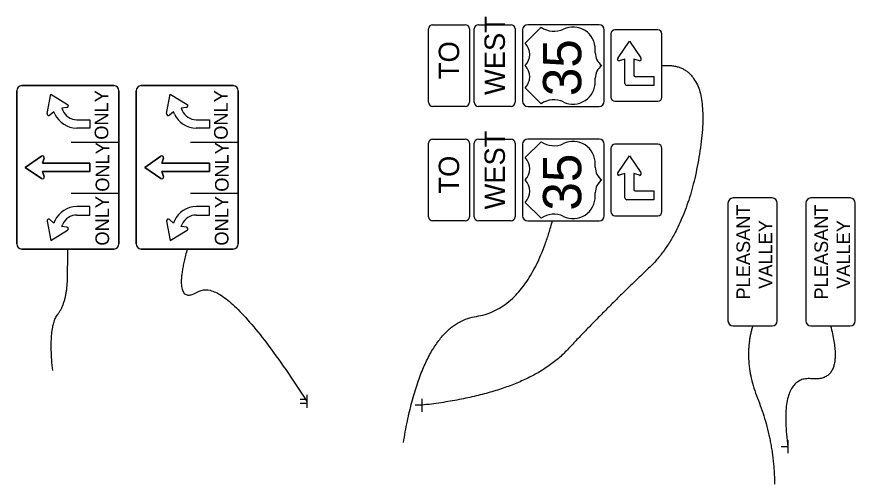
# Model space of a CAD drawing. Extents: x 1817563 to 1822411, y 498049 to 499279.
# Drawn here: x 1817747.4 to 1817952.7, y 499164.3 to 499278.8 of the extents above; entities that cross this region are included whole.
import ezdxf

# ---------------------------------------------------------------- set-up
doc = ezdxf.new("R2010")
doc.units = 0
doc.layers.add('PM_X_Stop_Line', color=7, linetype='Continuous')
doc.layers.add('SC_Scratch2', color=7, linetype='Continuous')

msp = doc.modelspace()

# ---------------------------------------------------------------- linework, layer by layer
at = {"layer": 'PM_X_Stop_Line'}
for p, q in [((1817848.25, 499257.84), (1817848.25, 499275.84)), ((1817849.25, 499276.84), (1817857.25, 499276.84)), ((1817858.25, 499275.84), (1817858.25, 499257.84)), ((1817859.46, 499257.84), (1817859.46, 499275.84)), ((1817860.46, 499276.84), (1817868.46, 499276.84)), ((1817869.46, 499275.84), (1817869.46, 499257.84)), ((1817875.81, 499276.22), (1817871.9, 499272.31)), ((1817904.41, 499275.59), (1817893.91, 499275.59)), ((1817892.91, 499274.59), (1817892.91, 499259.09)), ((1817905.41, 499259.09), (1817905.41, 499274.59)), ((1817894.65, 499268.7), (1817897.44, 499272.78)), ((1817897.44, 499272.78), (1817900.24, 499268.7)), ((1817889.09, 499269.97), (1817889.09, 499270.75)), ((1817896.35, 499268.4), (1817894.94, 499267.99)), ((1817896.35, 499262.47), (1817896.35, 499268.4)), ((1817899.94, 499267.99), (1817898.54, 499268.4)), ((1817898.54, 499268.4), (1817898.54, 499264.5)), ((1817889.09, 499262.94), (1817889.09, 499263.72)), ((1817898.85, 499264.19), (1817903.38, 499264.19)), ((1817903.38, 499264.19), (1817903.38, 499262)), ((1817871.9, 499261.37), (1817875.81, 499257.47)), ((1817896.35, 499262.47), (1817896.35, 499262.47)), ((1817903.38, 499262), (1817896.82, 499262)), ((1817784.13, 499255.08), (1817785.01, 499259.84)), ((1817785.01, 499259.84), (1817789.14, 499257.31)), ((1817857.25, 499256.84), (1817849.25, 499256.84)), ((1817868.46, 499256.84), (1817860.46, 499256.84)), ((1817893.91, 499258.09), (1817904.41, 499258.09)), ((1817785.78, 499255.54), (1817784.81, 499254.69)), ((1817786.04, 499254.96), (1817785.78, 499255.54)), ((1817788.97, 499256.54), (1817787.69, 499256.39)), ((1817787.69, 499256.39), (1817787.94, 499255.81)), ((1817791.37, 499253.59), (1817794.6, 499253.59)), ((1817794.6, 499253.59), (1817794.6, 499251.5)), ((1817794.6, 499251.5), (1817791.37, 499251.5)), ((1817790.01, 499248.06), (1817801.68, 499248.06)), ((1817778.76, 499241.92), (1817782.75, 499244.66)), ((1817782.75, 499244.66), (1817778.76, 499241.92)), ((1817783.38, 499244.19), (1817783, 499242.96)), ((1817783, 499242.96), (1817783.38, 499244.19)), ((1817783, 499242.96), (1817794.6, 499242.96)), ((1817794.6, 499242.96), (1817783, 499242.96)), ((1817794.6, 499242.96), (1817794.6, 499240.88)), ((1817794.6, 499240.88), (1817794.6, 499242.96)), ((1817782.75, 499239.18), (1817778.76, 499241.92)), ((1817778.76, 499241.92), (1817782.75, 499239.18)), ((1817794.6, 499240.88), (1817783, 499240.88)), ((1817783, 499240.88), (1817783.38, 499239.65)), ((1817783.38, 499239.65), (1817783, 499240.88)), ((1817783, 499240.88), (1817794.6, 499240.88)), ((1817790.01, 499235.56), (1817801.68, 499235.56)), ((1817794.6, 499232.34), (1817791.37, 499232.34)), ((1817794.6, 499230.25), (1817794.6, 499232.34)), ((1817791.37, 499230.25), (1817794.6, 499230.25)), ((1817784.13, 499228.75), (1817785.01, 499224)), ((1817785.78, 499228.29), (1817784.81, 499229.14)), ((1817786.04, 499228.88), (1817785.78, 499228.29)), ((1817785.01, 499224), (1817789.14, 499226.53)), ((1817787.69, 499227.45), (1817787.94, 499228.03)), ((1817788.97, 499227.3), (1817787.69, 499227.45)), ((1817818.46, 499185.09), (1817816.86, 499185.09)), ((1817818.46, 499186.21), (1817818.46, 499183.01)), ((1817846.6, 499185.27), (1817846.6, 499182.07)), ((1817818.46, 499184.13), (1817816.86, 499184.13)), ((1817818.46, 499184.61), (1817818.46, 499184.61)), ((1817818.46, 499184.61), (1817818.46, 499184.61)), ((1817846.6, 499183.67), (1817845, 499183.67)), ((1817936.23, 499175.13), (1817936.23, 499171.93)), ((1817936.23, 499173.53), (1817934.63, 499173.53))]:
    msp.add_line(p, q, dxfattribs=at)
for points in [[(1817871.28, 499275.59), (1817871.28, 499258.09)], [(1817890.03, 499276.84), (1817872.53, 499276.84)], [(1817891.28, 499258.09), (1817891.28, 499275.59)], [(1817777.93, 499261.92), (1817800.43, 499261.92)], [(1817800.43, 499261.92), (1817777.93, 499261.92)], [(1817776.68, 499223.17), (1817776.68, 499260.67)], [(1817776.68, 499260.67), (1817776.68, 499223.17)], [(1817801.68, 499260.67), (1817801.68, 499223.17)], [(1817801.68, 499223.17), (1817801.68, 499260.67)], [(1817872.53, 499256.84), (1817890.03, 499256.84)], [(1817951.48, 499234.42), (1817941.89, 499234.42)], [(1817940.64, 499233.17), (1817940.64, 499204.34)], [(1817952.73, 499204.34), (1817952.73, 499233.17)], [(1817800.43, 499221.92), (1817777.93, 499221.92)], [(1817777.93, 499221.92), (1817800.43, 499221.92)], [(1817941.89, 499203.09), (1817951.48, 499203.09)]]:
    msp.add_lwpolyline(points, dxfattribs=at)
for centre, radius, start, end in [((1817849.25, 499275.84), 1, 90, 180), ((1817857.25, 499275.84), 1, 0, 90), ((1817860.46, 499275.84), 1, 90, 180), ((1817868.46, 499275.84), 1, 0, 90), ((1817872.53, 499275.59), 1.25, 90, 180), ((1817878.95, 499280.7), 5.47, 234.9991, 295.4529), ((1817883.62, 499270.81), 5.47, 359.3617, 115.1681), ((1817890.03, 499275.59), 1.25, 0, 90), ((1817893.91, 499274.59), 1, 90, 180), ((1817904.41, 499274.59), 1, 0, 90), ((1817869.11, 499269.58), 3.91, 315.573, 44.427), ((1817893, 499269.97), 3.91, 180, 233.1301), ((1817894.94, 499268.4), 0.417, 135.0001, 269.9983), ((1817899.94, 499268.4), 0.417, 269.9983, 44.9999), ((1817869.11, 499264.11), 3.91, 315.573, 44.427), ((1817893, 499263.72), 3.91, 126.8699, 180), ((1817898.85, 499264.5), 0.312, 180, 270), ((1817777.93, 499260.67), 1.25, 90, 180), ((1817777.93, 499260.67), 1.25, 90, 180), ((1817800.43, 499260.67), 1.25, 360, 90), ((1817800.43, 499260.67), 1.25, 0, 90), ((1817883.62, 499262.87), 5.47, 244.8319, 0.6383), ((1817896.82, 499262.47), 0.469, 180, 270), ((1817893.91, 499259.09), 1, 180, 270), ((1817904.41, 499259.09), 1, 270, 0), ((1817788.92, 499256.95), 0.417, 276.5948, 58.4729), ((1817849.25, 499257.84), 1, 180, 270), ((1817857.25, 499257.84), 1, 270, 360), ((1817860.46, 499257.84), 1, 180, 270), ((1817868.46, 499257.84), 1, 270, 360), ((1817872.53, 499258.09), 1.25, 180, 270), ((1817878.95, 499252.99), 5.47, 64.5471, 125.0009), ((1817890.03, 499258.09), 1.25, 270, 360), ((1817784.54, 499255.01), 0.417, 169.4403, 311.3184), ((1817791.37, 499257.34), 5.83, 203.9101, 270), ((1817791.37, 499257.34), 3.75, 203.8986, 270), ((1817782.98, 499244.31), 0.417, 342.6382, 124.5163), ((1817782.98, 499244.31), 0.417, 342.6382, 124.5163), ((1817782.98, 499239.52), 0.417, 235.4837, 17.3618), ((1817782.98, 499239.52), 0.417, 235.4837, 17.3618), ((1817941.89, 499233.17), 1.25, 90, 180), ((1817951.48, 499233.17), 1.25, 360, 90), ((1817791.37, 499226.5), 5.83, 90, 156.0899), ((1817791.37, 499226.5), 3.75, 90, 156.1014), ((1817784.54, 499228.83), 0.417, 48.6816, 190.5597), ((1817788.92, 499226.89), 0.417, 301.5271, 83.4052), ((1817777.93, 499223.17), 1.25, 180, 270), ((1817777.93, 499223.17), 1.25, 180, 270), ((1817800.43, 499223.17), 1.25, 270, 360), ((1817800.43, 499223.17), 1.25, 270, 0), ((1817941.89, 499204.34), 1.25, 180, 270), ((1817951.48, 499204.34), 1.25, 270, 360)]:
    msp.add_arc(centre, radius, start, end, dxfattribs=at)
for points in [[(1817905.41, 499266.84), (1817917.72, 499267.86), (1817912.05, 499226.55), (1817891.94, 499207.57), (1817872.26, 499186.6), (1817846.6, 499183.67)], [(1817789.18, 499221.92), (1817785.22, 499207.53), (1817798.68, 499215.5), (1817818.46, 499184.61)], [(1817946.69, 499203.09), (1817950.33, 499189.3), (1817933.88, 499191.01), (1817936.23, 499173.53)]]:
    msp.add_open_spline(points, degree=2, dxfattribs=at)
at = {"layer": 'SC_Scratch2'}
for p, q in [((1817754.89, 499255.08), (1817755.78, 499259.84)), ((1817755.78, 499259.84), (1817759.9, 499257.31)), ((1817756.54, 499255.54), (1817755.57, 499254.69)), ((1817756.8, 499254.96), (1817756.54, 499255.54)), ((1817759.73, 499256.54), (1817758.45, 499256.39)), ((1817758.45, 499256.39), (1817758.7, 499255.81)), ((1817762.13, 499253.59), (1817765.36, 499253.59)), ((1817765.36, 499253.59), (1817765.36, 499251.5)), ((1817765.36, 499251.5), (1817762.13, 499251.5)), ((1817849.25, 499248.82), (1817857.25, 499248.82)), ((1817860.46, 499248.82), (1817868.46, 499248.82)), ((1817760.78, 499248.06), (1817772.44, 499248.06)), ((1817848.25, 499229.82), (1817848.25, 499247.82)), ((1817858.25, 499247.82), (1817858.25, 499229.82)), ((1817859.46, 499229.82), (1817859.46, 499247.82)), ((1817869.46, 499247.82), (1817869.46, 499229.82)), ((1817875.81, 499248.2), (1817871.9, 499244.29)), ((1817904.41, 499247.57), (1817893.91, 499247.57)), ((1817749.53, 499241.92), (1817753.51, 499244.66)), ((1817753.51, 499244.66), (1817749.53, 499241.92)), ((1817892.91, 499246.57), (1817892.91, 499231.07)), ((1817894.65, 499240.68), (1817897.44, 499244.76)), ((1817897.44, 499244.76), (1817900.24, 499240.68)), ((1817905.41, 499231.07), (1817905.41, 499246.57)), ((1817754.14, 499244.19), (1817753.76, 499242.96)), ((1817753.76, 499242.96), (1817754.14, 499244.19)), ((1817753.76, 499242.96), (1817765.36, 499242.96)), ((1817765.36, 499242.96), (1817753.76, 499242.96)), ((1817765.36, 499242.96), (1817765.36, 499240.88)), ((1817765.36, 499240.88), (1817765.36, 499242.96)), ((1817889.09, 499241.95), (1817889.09, 499242.73)), ((1817753.51, 499239.18), (1817749.53, 499241.92)), ((1817749.53, 499241.92), (1817753.51, 499239.18)), ((1817765.36, 499240.88), (1817753.76, 499240.88)), ((1817753.76, 499240.88), (1817754.14, 499239.65)), ((1817754.14, 499239.65), (1817753.76, 499240.88)), ((1817753.76, 499240.88), (1817765.36, 499240.88)), ((1817896.35, 499240.38), (1817894.94, 499239.97)), ((1817896.35, 499234.45), (1817896.35, 499240.38)), ((1817899.94, 499239.97), (1817898.54, 499240.38)), ((1817898.54, 499240.38), (1817898.54, 499236.48)), ((1817760.78, 499235.56), (1817772.44, 499235.56)), ((1817889.09, 499234.92), (1817889.09, 499235.7)), ((1817896.35, 499234.45), (1817896.35, 499234.45)), ((1817898.85, 499236.17), (1817903.38, 499236.17)), ((1817903.38, 499236.17), (1817903.38, 499233.98)), ((1817765.36, 499232.34), (1817762.13, 499232.34)), ((1817765.36, 499230.25), (1817765.36, 499232.34)), ((1817871.9, 499233.35), (1817875.81, 499229.45)), ((1817903.38, 499233.98), (1817896.82, 499233.98)), ((1817762.13, 499230.25), (1817765.36, 499230.25)), ((1817754.89, 499228.75), (1817755.78, 499224)), ((1817756.54, 499228.29), (1817755.57, 499229.14)), ((1817756.8, 499228.88), (1817756.54, 499228.29)), ((1817857.25, 499228.82), (1817849.25, 499228.82)), ((1817868.46, 499228.82), (1817860.46, 499228.82)), ((1817893.91, 499230.07), (1817904.41, 499230.07)), ((1817755.78, 499224), (1817759.9, 499226.53)), ((1817758.45, 499227.45), (1817758.7, 499228.03)), ((1817759.73, 499227.3), (1817758.45, 499227.45))]:
    msp.add_line(p, q, dxfattribs=at)
for points in [[(1817748.69, 499261.92), (1817771.19, 499261.92)], [(1817771.19, 499261.92), (1817748.69, 499261.92)], [(1817747.44, 499223.17), (1817747.44, 499260.67)], [(1817747.44, 499260.67), (1817747.44, 499223.17)], [(1817772.44, 499260.67), (1817772.44, 499223.17)], [(1817772.44, 499223.17), (1817772.44, 499260.67)], [(1817890.03, 499248.82), (1817872.53, 499248.82)], [(1817871.28, 499247.57), (1817871.28, 499230.07)], [(1817891.28, 499230.07), (1817891.28, 499247.57)], [(1817932.4, 499234.42), (1817922.81, 499234.42)], [(1817921.56, 499233.17), (1817921.56, 499204.34)], [(1817933.65, 499204.34), (1817933.65, 499233.17)], [(1817872.53, 499228.82), (1817890.03, 499228.82)], [(1817771.19, 499221.92), (1817748.69, 499221.92)], [(1817748.69, 499221.92), (1817771.19, 499221.92)], [(1817922.81, 499203.09), (1817932.4, 499203.09)]]:
    msp.add_lwpolyline(points, dxfattribs=at)
for centre, radius, start, end in [((1817748.69, 499260.67), 1.25, 90, 180), ((1817748.69, 499260.67), 1.25, 90, 180), ((1817771.19, 499260.67), 1.25, 360, 90), ((1817771.19, 499260.67), 1.25, 0, 90), ((1817759.68, 499256.95), 0.417, 276.5948, 58.4729), ((1817755.3, 499255.01), 0.417, 169.4403, 311.3184), ((1817762.13, 499257.34), 5.83, 203.9101, 270), ((1817762.13, 499257.34), 3.75, 203.8986, 270), ((1817849.25, 499247.82), 1, 90, 180), ((1817857.25, 499247.82), 1, 0, 90), ((1817860.46, 499247.82), 1, 90, 180), ((1817868.46, 499247.82), 1, 0, 90), ((1817872.53, 499247.57), 1.25, 90, 180), ((1817890.03, 499247.57), 1.25, 0, 90), ((1817878.95, 499252.68), 5.47, 234.9991, 295.4529), ((1817883.62, 499242.79), 5.47, 359.3617, 115.1681), ((1817893.91, 499246.57), 1, 90, 180), ((1817904.41, 499246.57), 1, 0, 90), ((1817753.75, 499244.31), 0.417, 342.6382, 124.5163), ((1817753.75, 499244.31), 0.417, 342.6382, 124.5163), ((1817869.11, 499241.56), 3.91, 315.573, 44.427), ((1817893, 499241.95), 3.91, 180, 233.1301), ((1817894.94, 499240.38), 0.417, 135.0001, 269.9983), ((1817899.94, 499240.38), 0.417, 269.9983, 44.9999), ((1817753.75, 499239.52), 0.417, 235.4837, 17.3618), ((1817753.75, 499239.52), 0.417, 235.4837, 17.3618), ((1817869.11, 499236.09), 3.91, 315.573, 44.427), ((1817893, 499235.7), 3.91, 126.8699, 180), ((1817898.85, 499236.48), 0.312, 180, 270), ((1817883.62, 499234.85), 5.47, 244.8319, 0.6383), ((1817896.82, 499234.45), 0.469, 180, 270), ((1817922.81, 499233.17), 1.25, 90, 180), ((1817932.4, 499233.17), 1.25, 360, 90), ((1817762.13, 499226.5), 5.83, 90, 156.0899), ((1817762.13, 499226.5), 3.75, 90, 156.1014), ((1817878.95, 499224.97), 5.47, 64.5471, 125.0009), ((1817893.91, 499231.07), 1, 180, 270), ((1817904.41, 499231.07), 1, 270, 0), ((1817755.3, 499228.83), 0.417, 48.6816, 190.5597), ((1817849.25, 499229.82), 1, 180, 270), ((1817857.25, 499229.82), 1, 270, 360), ((1817860.46, 499229.82), 1, 180, 270), ((1817868.46, 499229.82), 1, 270, 360), ((1817872.53, 499230.07), 1.25, 180, 270), ((1817890.03, 499230.07), 1.25, 270, 360), ((1817759.68, 499226.89), 0.417, 301.5271, 83.4052), ((1817748.69, 499223.17), 1.25, 180, 270), ((1817748.69, 499223.17), 1.25, 180, 270), ((1817771.19, 499223.17), 1.25, 270, 360), ((1817771.19, 499223.17), 1.25, 270, 0), ((1817922.81, 499204.34), 1.25, 180, 270), ((1817932.4, 499204.34), 1.25, 270, 360)]:
    msp.add_arc(centre, radius, start, end, dxfattribs=at)
for points in [[(1817842.1, 499174.54), (1817846.85, 499203.43), (1817872.8, 499207.36), (1817878.61, 499228.85)], [(1817756.24, 499192.14), (1817755.12, 499202.87), (1817759.83, 499208.98), (1817759.94, 499221.92), (1817759.94, 499221.92)], [(1817927.61, 499203.09), (1817925.05, 499194.65), (1817932.83, 499175.36), (1817932.98, 499164.33)]]:
    msp.add_open_spline(points, degree=2, dxfattribs=at)

# ---------------------------------------------------------------- texts
at = {"layer": 'PM_X_Stop_Line'}
for s, height, p in [('WEST', 5, (1817866.96, 499259.63)), ('TO', 5, (1817855.75, 499263.51)), ('  35', 9.375, (1817885.65, 499252.38)), ('ONLY', 3.333, (1817799.09, 499248.68)), ('ONLY', 3.333, (1817799.32, 499235.95)), ('ONLY', 3.333, (1817799.27, 499222.76)), ('PLEASANT ', 3.333, (1817946.06, 499209.55)), ('VALLEY', 3.333, (1817951.48, 499212.16))]:
    msp.add_text(s, height=height, rotation=90, dxfattribs=at).set_placement(p)
at = {"layer": 'SC_Scratch2'}
for s, height, p in [('ONLY', 3.333, (1817769.85, 499248.68)), ('WEST', 5, (1817866.96, 499231.61)), ('ONLY', 3.333, (1817770.08, 499235.95)), ('  35', 9.375, (1817885.65, 499224.36)), ('TO', 5, (1817855.75, 499235.49)), ('ONLY', 3.333, (1817770.04, 499222.76)), ('PLEASANT ', 3.333, (1817926.98, 499209.55)), ('VALLEY', 3.333, (1817932.4, 499212.16))]:
    msp.add_text(s, height=height, rotation=90, dxfattribs=at).set_placement(p)

doc.saveas('drawing.dxf')
